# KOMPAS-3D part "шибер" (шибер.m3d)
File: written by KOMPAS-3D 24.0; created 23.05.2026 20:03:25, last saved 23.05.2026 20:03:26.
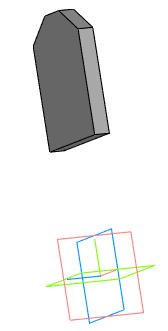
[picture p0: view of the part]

Document properties: Автор: R2D2; Полное имя файла: E:\Работа\Зайцев\GVKR1331E-1W-Fb-2P Задвижка шиберная DN.ru Ду50-300 Ру16-10-6\исходные материалы\DN50\шибер.m3d

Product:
- Part/product: шибер
    Масса: 0.384551
    Раздел спецификации: Прочие изделия
    Примечание: D040-08800

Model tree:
1. Эскиз:5  (with: Ребро.Элемент выдавливания:15, Ребро.Элемент выдавливания:2, Ребро.Скругление:10, Ребро.Элемент выдавливания:1)
2. Элемент выдавливания:6
     Расстояние 1 = 10

Referenced files in E:\Работа\Зайцев\GVKR1331E-1W-Fb-2P Задвижка шиберная DN.ru Ду50-300 Ру16-10-6\исходные материалы\DN50\: GVKR1331E-1W-Fb-2P Задвижка шиберная с выдвижным штоком DN.ru Ду50 Ру16.a3d
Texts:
  Затвор дисковый DN.ru Ду Ру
